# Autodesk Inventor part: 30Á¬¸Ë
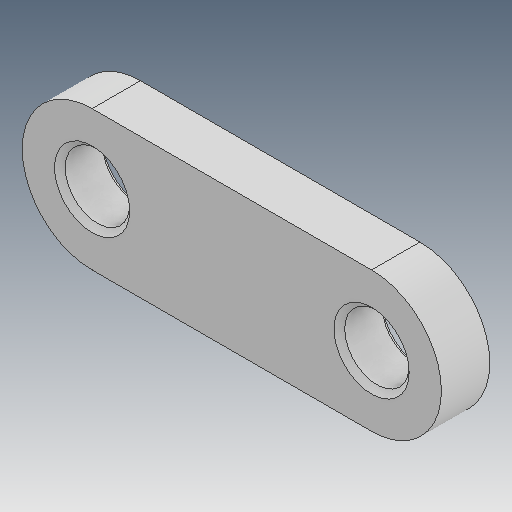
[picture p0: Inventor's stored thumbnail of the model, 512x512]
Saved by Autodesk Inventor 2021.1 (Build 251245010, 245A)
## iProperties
Created: 2019-04
Part Number: 30Á¬¸Ë
Material: Ogólny
Document SubType Name: Modeling
Designer: user
Density: 1 g/cm^3
Appearance: Domyślna
Author: user
Revision Number: ÈÎºÎ
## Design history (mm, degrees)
feature "ÊäÈë1"
node "Bryła1"
